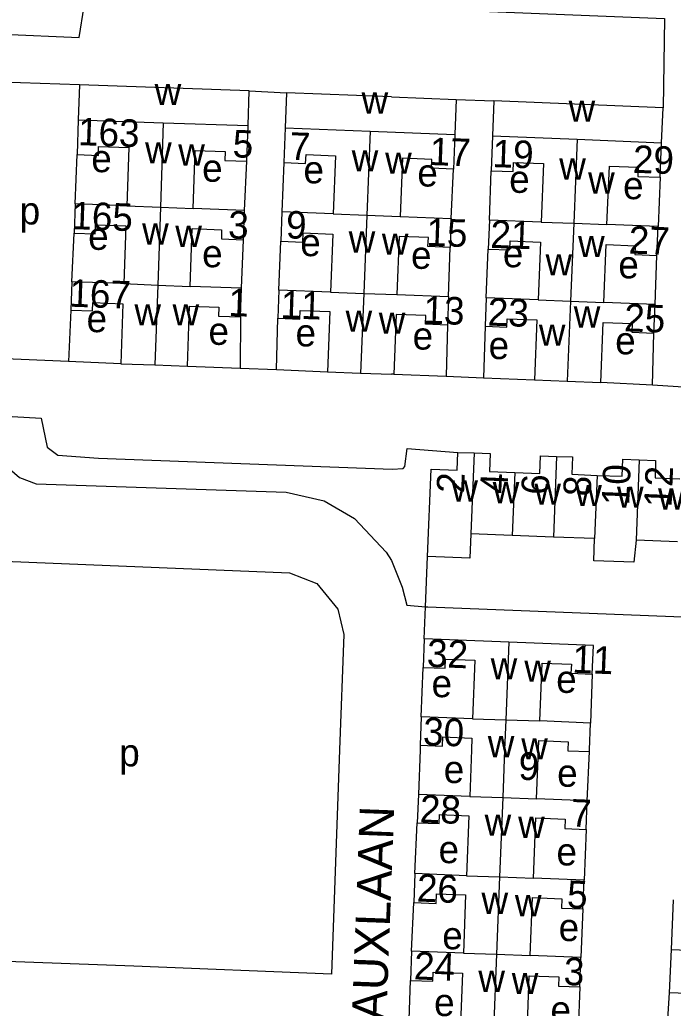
# Model space of a CAD drawing. Extents: x 159675 to 162108, y 386471 to 388472.
# Drawn here: x 160946 to 161040.9, y 387212.5 to 387356.1 of the extents above; entities that cross this region are included whole.
import ezdxf

# ---------------------------------------------------------------- set-up
doc = ezdxf.new("R2010")
doc.units = 0
for name, color, linetype in [('BLT_Basislijn', 7, 'Continuous'), ('BLT_Bebouwing', 7, 'Continuous'), ('BLT_Centroide', 7, 'Continuous'), ('BLT_Huisnummer', 7, 'Continuous'), ('BLT_Huisnummer_ tussenligend', 7, 'Continuous'), ('BLT_Onderverdeling_panden', 7, 'Continuous'), ('BLT_Straatnaam', 7, 'Continuous')]:
    doc.layers.add(name, color=color, linetype=linetype)

msp = doc.modelspace()

# ---------------------------------------------------------------- linework, layer by layer
at = {"layer": 'BLT_Basislijn'}
for p, q in [((160954.66, 387346.6), (160943.23, 387346.99)), ((160979.33, 387345.75), (160984.76, 387345.46)), ((161009.4, 387344.49), (161014.88, 387344.27)), ((160954.01, 387329.31), (160954.32, 387336.48)), ((160978.65, 387328.37), (160978.98, 387335.52)), ((160984.36, 387335.31), (160984.06, 387328.17)), ((161008.67, 387327.19), (161009, 387334.37)), ((161014.22, 387326.97), (161014.47, 387334.14)), ((161039.04, 387333.18), (161038.73, 387326.04)), ((160953.56, 387318.01), (160953.87, 387325.08)), ((160978.2, 387317.05), (160978.51, 387324.11)), ((160983.63, 387316.76), (160983.89, 387323.91)), ((161008.28, 387315.88), (161008.51, 387322.99)), ((161013.74, 387315.68), (161014.05, 387322.75)), ((161038.28, 387314.71), (161038.56, 387321.84)), ((160953.42, 387313.87), (160953.06, 387306.41)), ((160978.06, 387312.92), (160978.02, 387305.45)), ((160983.3, 387305.24), (160983.47, 387312.7)), ((161008.12, 387311.71), (161007.93, 387304.27)), ((161013.58, 387311.53), (161013.38, 387304.06)), ((161037.9, 387302.96), (161038.11, 387310.55)), ((160953.06, 387306.41), (160941.66, 387306.9)), ((160960.67, 387306.09), (160953.06, 387306.41)), ((160970.33, 387305.76), (160978.02, 387305.45)), ((160978.02, 387305.45), (160983.3, 387305.24)), ((160983.3, 387305.24), (160990.68, 387304.94)), ((161000.33, 387304.56), (161007.93, 387304.27)), ((161007.93, 387304.27), (161013.38, 387304.06)), ((161013.38, 387304.06), (161020.75, 387303.77)), ((161037.9, 387302.96), (161030.39, 387303.38)), ((161004.95, 387270.78), (161005.24, 387278.1)), ((161004.76, 387266.11), (161004.95, 387270.78)), ((161004.32, 387254.8), (161004.6, 387261.98)), ((161029.15, 387261.01), (161028.92, 387253.9)), ((161004.16, 387250.67), (161004.14, 387250)), ((161004.14, 387250), (161003.9, 387243.53)), ((161028.42, 387242.59), (161028.76, 387249.76)), ((161003.39, 387232.02), (161003.74, 387239.41)), ((161028.26, 387238.45), (161027.96, 387231.07)), ((161002.92, 387220.78), (161003.23, 387227.83)), ((161040.66, 387221), (161040.94, 387228.2)), ((161027.8, 387226.9), (161027.52, 387219.83)), ((160962.54, 387218.58), (160934, 387219.65)), ((161002.5, 387209.36), (161002.75, 387216.51)), ((161027.35, 387215.56), (161027.08, 387208.44))]:
    msp.add_line(p, q, dxfattribs=at)
for points in [[(160943.5, 387353.98), (160954.59, 387353.47), (160955.32, 387358.02), (160956.82, 387359.41), (160957.39, 387359.57), (161039.67, 387356.23), (161039.45, 387343.28)], [(161043.75, 387314.9), (161043.16, 387302.66), (161037.9, 387302.96)], [(160941.45, 387298.63), (160941.64, 387295.23), (160943.77, 387291.48), (160945.93, 387289.57), (160948.35, 387288.66), (160984.7, 387287.44), (160990.23, 387286.16), (160994.63, 387283.62), (160999.2, 387278.72), (160999.97, 387277.51), (161001.53, 387273.66), (161002.23, 387271.02), (161004.95, 387270.78)], [(160941.45, 387298.63), (160949.1, 387298.21), (160949.94, 387293.99), (160951.5, 387292.8), (160957.41, 387292.36), (161000.11, 387290.8), (161001.67, 387290.86), (161001.91, 387291.15), (161002.26, 387293.76), (161009.65, 387293.22)], [(161004.95, 387270.78), (161005.27, 387270.76), (161101.43, 387266.99), (161101.69, 387277.88)], [(160936.6, 387277.69), (160985.17, 387275.74), (160989.15, 387274.17), (160992.18, 387270.46), (160993.05, 387266.78), (160992.45, 387250)], [(160992.45, 387250), (160991.28, 387217.42), (160962.54, 387218.58)], [(161026.76, 387197.03), (161032.52, 387197.07), (161035.77, 387197.5), (161038.7, 387199.6), (161039.59, 387202.34), (161040.4, 387214.71)]]:
    msp.add_lwpolyline(points, dxfattribs=at)
at = {"layer": 'BLT_Bebouwing'}
for p, q in [((160954.66, 387346.6), (160954.49, 387341.54)), ((160979.33, 387345.75), (160954.66, 387346.6)), ((160979.16, 387340.7), (160979.33, 387345.75)), ((160984.76, 387345.46), (160984.56, 387340.39)), ((161000, 387344.86), (160984.76, 387345.46)), ((161000, 387344.86), (161009.4, 387344.49)), ((161009.4, 387344.49), (161009.2, 387339.42)), ((161014.88, 387344.27), (161014.68, 387339.21)), ((161039.45, 387343.28), (161014.88, 387344.27)), ((161039.24, 387338.21), (161039.45, 387343.28)), ((160954.49, 387341.54), (160954.32, 387336.48)), ((160978.98, 387335.52), (160979.16, 387340.7)), ((160984.56, 387340.39), (160984.36, 387335.31)), ((161009.2, 387339.42), (161009, 387334.37)), ((161014.68, 387339.21), (161014.47, 387334.14)), ((161039.04, 387333.18), (161039.24, 387338.21)), ((160954.01, 387329.31), (160953.87, 387325.08)), ((160961.53, 387329.05), (160954.01, 387329.31)), ((160978.65, 387328.37), (160971.2, 387328.63)), ((160978.51, 387324.11), (160978.65, 387328.37)), ((160984.06, 387328.17), (160983.89, 387323.91)), ((160991.54, 387327.88), (160984.06, 387328.17)), ((161001.26, 387327.48), (161008.67, 387327.19)), ((161008.67, 387327.19), (161008.51, 387322.99)), ((161014.22, 387326.97), (161014.05, 387322.75)), ((161021.75, 387326.66), (161014.22, 387326.97)), ((161038.73, 387326.04), (161031.29, 387326.34)), ((161038.56, 387321.84), (161038.73, 387326.04)), ((160953.56, 387318.01), (160953.42, 387313.87)), ((160961.11, 387317.76), (160953.56, 387318.01)), ((160978.2, 387317.05), (160970.76, 387317.3)), ((160978.06, 387312.92), (160978.2, 387317.05)), ((160983.63, 387316.76), (160983.47, 387312.7)), ((160991.12, 387316.47), (160983.63, 387316.76)), ((161000.79, 387316.17), (161008.28, 387315.88)), ((161008.28, 387315.88), (161008.12, 387311.71)), ((161013.74, 387315.68), (161013.58, 387311.53)), ((161021.3, 387315.37), (161013.74, 387315.68)), ((161038.28, 387314.71), (161030.82, 387315.01)), ((161038.11, 387310.55), (161038.28, 387314.71)), ((160960.67, 387306.09), (160965.63, 387305.92)), ((160965.63, 387305.92), (160970.33, 387305.76)), ((160990.68, 387304.94), (160995.5, 387304.75)), ((160995.5, 387304.75), (161000, 387304.58)), ((161000.33, 387304.56), (161000, 387304.58)), ((161020.75, 387303.77), (161025.53, 387303.58)), ((161025.53, 387303.58), (161030.39, 387303.38)), ((161009.65, 387293.22), (161011.99, 387293.13)), ((161017.53, 387281.16), (161011.53, 387281.39)), ((161023.52, 387280.92), (161017.53, 387281.16)), ((161029.5, 387280.69), (161023.52, 387280.92)), ((161041.54, 387280.22), (161035.54, 387280.46)), ((161004.76, 387266.11), (161004.6, 387261.98)), ((161017.04, 387265.63), (161004.76, 387266.11)), ((161004.32, 387254.8), (161004.16, 387250.67)), ((161011.74, 387254.51), (161004.32, 387254.8)), ((161028.92, 387253.9), (161021.54, 387254.2)), ((161028.77, 387250), (161028.92, 387253.9)), ((161011.62, 387250), (161011.35, 387243.23)), ((161021.08, 387242.88), (161021.36, 387250)), ((161028.76, 387249.76), (161028.77, 387250)), ((161003.9, 387243.53), (161003.74, 387239.41)), ((161011.35, 387243.23), (161003.9, 387243.53)), ((161028.42, 387242.59), (161021.08, 387242.88)), ((161028.26, 387238.45), (161028.42, 387242.59)), ((161003.39, 387232.02), (161003.23, 387227.83)), ((161010.88, 387231.72), (161003.39, 387232.02)), ((161027.96, 387231.07), (161020.62, 387231.36)), ((161027.8, 387226.9), (161027.96, 387231.07)), ((161002.92, 387220.78), (161002.75, 387216.51)), ((161010.43, 387220.49), (161002.92, 387220.78)), ((161040.4, 387214.71), (161040.66, 387221)), ((161040.66, 387221), (161048.8, 387220.67)), ((161027.52, 387219.83), (161020.15, 387220.12)), ((161027.35, 387215.56), (161027.52, 387219.83)), ((161064.83, 387213.7), (161040.4, 387214.71))]:
    msp.add_line(p, q, dxfattribs=at)
for points in [[(160954.32, 387336.48), (160957.4, 387336.37), (160957.44, 387337.65), (160961.82, 387337.5), (160961.53, 387329.05)], [(160971.2, 387328.63), (160971.49, 387337.08), (160975.81, 387336.93), (160975.77, 387335.63), (160978.98, 387335.52)], [(160984.36, 387335.31), (160987.52, 387335.19), (160987.57, 387336.49), (160991.87, 387336.32), (160991.54, 387327.88)], [(161009, 387334.37), (161005.78, 387334.49), (161005.83, 387335.78), (161001.59, 387335.95), (161001.26, 387327.48)], [(161014.47, 387334.14), (161017.67, 387334.01), (161017.73, 387335.34), (161022.09, 387335.17), (161021.75, 387326.66)], [(161031.29, 387326.34), (161031.64, 387334.81), (161035.85, 387334.64), (161035.8, 387333.31), (161039.04, 387333.18)], [(160953.87, 387325.08), (160956.96, 387324.97), (160957.01, 387326.29), (160961.39, 387326.14), (160961.11, 387317.76)], [(160970.76, 387317.3), (160971.05, 387325.72), (160975.31, 387325.57), (160975.27, 387324.22), (160978.51, 387324.11)], [(160983.89, 387323.91), (160987.1, 387323.78), (160987.15, 387325.1), (160991.45, 387324.93), (160991.12, 387316.47)], [(161008.51, 387322.99), (161005.29, 387323.11), (161005.35, 387324.43), (161001.12, 387324.6), (161000.79, 387316.17)], [(161014.05, 387322.75), (161017.2, 387322.62), (161017.25, 387323.96), (161021.64, 387323.78), (161021.3, 387315.37)], [(161030.82, 387315.01), (161031.16, 387323.42), (161035.41, 387323.24), (161035.36, 387321.97), (161038.56, 387321.84)], [(160953.42, 387313.87), (160956.54, 387313.76), (160956.58, 387314.97), (160960.96, 387314.82), (160960.67, 387306.09)], [(160970.33, 387305.76), (160970.63, 387314.45), (160974.89, 387314.31), (160974.84, 387313.03), (160978.06, 387312.92)], [(160983.47, 387312.7), (160986.68, 387312.57), (160986.73, 387313.84), (160991.02, 387313.67), (160990.68, 387304.94)], [(161008.12, 387311.71), (161004.91, 387311.84), (161004.96, 387313.08), (161000.67, 387313.24), (161000.33, 387304.56)], [(161013.58, 387311.53), (161016.76, 387311.4), (161016.81, 387312.63), (161021.11, 387312.45), (161020.75, 387303.77)], [(161030.39, 387303.38), (161030.75, 387312.11), (161034.96, 387311.94), (161034.91, 387310.68), (161038.11, 387310.55)], [(161005.24, 387278.1), (161005.73, 387290.78), (161009.55, 387290.63), (161009.65, 387293.22)], [(161011.99, 387293.13), (161014.33, 387293.04), (161014.22, 387290.43), (161017.89, 387290.29)], [(161017.89, 387290.29), (161021.55, 387290.14), (161021.65, 387292.73), (161023.98, 387292.64)], [(161023.98, 387292.64), (161026.3, 387292.55), (161026.21, 387290.03), (161029.86, 387289.88)], [(161029.86, 387289.88), (161033.51, 387289.74), (161033.61, 387292.22), (161035.99, 387292.13)], [(161035.99, 387292.13), (161038.37, 387292.03), (161038.28, 387289.51), (161041.9, 387289.37)], [(161011.53, 387281.39), (161011.39, 387277.86), (161005.24, 387278.1)], [(161035.54, 387280.46), (161035.19, 387277.26), (161029.38, 387277.48), (161029.5, 387280.69)], [(161029.15, 387261.01), (161029.32, 387265.14), (161017.04, 387265.63)], [(161004.6, 387261.98), (161007.78, 387261.86), (161007.83, 387263.18), (161012.08, 387263.01), (161011.74, 387254.51)], [(161021.54, 387254.2), (161021.87, 387262.62), (161026.12, 387262.46), (161026.07, 387261.13), (161029.15, 387261.01)], [(161004.16, 387250.67), (161007.38, 387250.54), (161007.43, 387251.89), (161011.68, 387251.72), (161011.62, 387250)], [(161021.36, 387250), (161021.42, 387251.36), (161025.65, 387251.19), (161025.61, 387250)], [(161025.61, 387250), (161025.6, 387249.88), (161028.76, 387249.76)], [(161003.74, 387239.41), (161006.92, 387239.29), (161006.98, 387240.6), (161011.22, 387240.43), (161010.88, 387231.72)], [(161020.62, 387231.36), (161020.97, 387240.12), (161025.22, 387239.95), (161025.17, 387238.57), (161028.26, 387238.45)], [(161003.23, 387227.83), (161006.46, 387227.7), (161006.52, 387229.08), (161010.76, 387228.92), (161010.43, 387220.49)], [(161020.15, 387220.12), (161020.49, 387228.54), (161024.76, 387228.37), (161024.71, 387227.02), (161027.8, 387226.9)], [(161002.75, 387216.51), (161005.99, 387216.38), (161006.04, 387217.71), (161010.29, 387217.54), (161009.95, 387209.07)], [(161019.68, 387208.73), (161020.01, 387217.18), (161024.32, 387217.01), (161024.27, 387215.68), (161027.35, 387215.56)]]:
    msp.add_lwpolyline(points, dxfattribs=at)
at = {"layer": 'BLT_Onderverdeling_panden'}
for p, q in [((160954.49, 387341.54), (160966.83, 387341.11)), ((160966.83, 387341.11), (160966.41, 387328.84)), ((160966.83, 387341.11), (160979.16, 387340.7)), ((160984.56, 387340.39), (160996.88, 387339.9)), ((160996.88, 387339.9), (160996.4, 387327.68)), ((160996.88, 387339.9), (161009.2, 387339.42)), ((161014.68, 387339.21), (161026.96, 387338.71)), ((161026.96, 387338.71), (161026.46, 387326.5)), ((161026.96, 387338.71), (161039.24, 387338.21)), ((160961.53, 387329.05), (160966.41, 387328.84)), ((160966.41, 387328.84), (160966.02, 387317.52)), ((160966.41, 387328.84), (160971.2, 387328.63)), ((160991.54, 387327.88), (160996.4, 387327.68)), ((160996.4, 387327.68), (160995.95, 387316.32)), ((160996.4, 387327.68), (161001.26, 387327.48)), ((161021.75, 387326.66), (161026.46, 387326.5)), ((161026.46, 387326.5), (161026.01, 387315.2)), ((161026.46, 387326.5), (161031.29, 387326.34)), ((160961.11, 387317.76), (160966.02, 387317.52)), ((160966.02, 387317.52), (160965.63, 387305.92)), ((160966.02, 387317.52), (160970.76, 387317.3)), ((160991.12, 387316.47), (160995.95, 387316.32)), ((160995.95, 387316.32), (160995.5, 387304.75)), ((160995.95, 387316.32), (161000.79, 387316.17)), ((161021.3, 387315.37), (161026.01, 387315.2)), ((161026.01, 387315.2), (161025.53, 387303.58)), ((161026.01, 387315.2), (161030.82, 387315.01)), ((161011.99, 387293.13), (161011.53, 387281.39)), ((161023.98, 387292.64), (161023.52, 387280.92)), ((161035.99, 387292.13), (161035.54, 387280.46)), ((161017.89, 387290.29), (161017.53, 387281.16)), ((161029.86, 387289.88), (161029.5, 387280.69)), ((161017.04, 387265.63), (161016.59, 387254.36)), ((161011.74, 387254.51), (161016.59, 387254.36)), ((161016.59, 387254.36), (161016.42, 387250)), ((161016.59, 387254.36), (161021.54, 387254.2)), ((161016.42, 387250), (161016.15, 387243.06)), ((161011.35, 387243.23), (161016.15, 387243.06)), ((161016.15, 387243.06), (161015.69, 387231.54)), ((161016.15, 387243.06), (161021.08, 387242.88)), ((161010.88, 387231.72), (161015.69, 387231.54)), ((161015.69, 387231.54), (161015.25, 387220.3)), ((161015.69, 387231.54), (161020.62, 387231.36)), ((161010.43, 387220.49), (161015.25, 387220.3)), ((161015.25, 387220.3), (161014.8, 387208.9)), ((161015.25, 387220.3), (161020.15, 387220.12))]:
    msp.add_line(p, q, dxfattribs=at)

# ---------------------------------------------------------------- texts
at = {"layer": 'BLT_Centroide'}
for s, p in [('w', (160965.58, 387343.66)), ('w', (160995.64, 387342.44)), ('w', (161025.72, 387341.25)), ('w', (160964.19, 387335.19)), ('e', (160956.38, 387333.92)), ('w', (160969.01, 387334.88)), ('w', (160994.21, 387334.03)), ('w', (160999.07, 387333.69)), ('e', (160972.48, 387332.53)), ('e', (160987.2, 387332.3)), ('w', (161024.36, 387332.84)), ('e', (161003.75, 387331.84)), ('e', (161017.09, 387330.92)), ('w', (161028.56, 387330.82)), ('e', (161033.64, 387330)), ('p', (160945.97, 387326.33)), ('e', (160955.92, 387322.64)), ('w', (160963.76, 387323.41)), ('w', (160968.58, 387323.06)), ('w', (160993.77, 387322.25)), ('e', (160986.74, 387321.72)), ('w', (160998.59, 387321.94)), ('w', (161027.1, 387321.58)), ('e', (160972.48, 387320.11)), ('e', (161002.83, 387319.88)), ('e', (161016.17, 387320.11)), ('w', (161022.37, 387318.94)), ('e', (161032.95, 387318.5)), ('e', (160955.69, 387310.68)), ('w', (160962.64, 387311.66)), ('w', (160968.18, 387311.66)), ('w', (160993.32, 387310.75)), ('w', (161026.47, 387311.36)), ('w', (160998.14, 387310.44)), ('e', (160973.4, 387308.84)), ('e', (160986.05, 387308.61)), ('e', (161003.06, 387308.15)), ('w', (161021.4, 387308.72)), ('e', (161014.1, 387306.77)), ('e', (161032.49, 387307.46)), ('w', (161008.69, 387286.08)), ('w', (161014.7, 387285.84)), ('w', (161020.75, 387285.61)), ('w', (161026.69, 387285.41)), ('w', (161032.75, 387285.17)), ('w', (161038.72, 387284.92)), ('w', (161014.4, 387260.25)), ('w', (161019.29, 387259.91)), ('e', (161005.81, 387257.65)), ('e', (161023.92, 387258.28)), ('w', (161013.98, 387248.94)), ('p', (160960.44, 387247.6)), ('w', (161018.84, 387248.62)), ('e', (161007.58, 387245.18)), ('e', (161024.06, 387244.64)), ('w', (161013.52, 387237.53)), ('w', (161018.39, 387237.22)), ('e', (161006.83, 387233.54)), ('e', (161023.96, 387233.21)), ('w', (161013.07, 387226.16)), ('w', (161017.92, 387225.84)), ('e', (161024.28, 387222.22)), ('e', (161007.37, 387221.03)), ('w', (161012.61, 387214.84)), ('w', (161017.46, 387214.53)), ('e', (161006.18, 387211.33)), ('e', (161023.09, 387210.25))]:
    msp.add_text(s, height=4, dxfattribs=at).set_placement(p)
at = {"layer": 'BLT_Huisnummer'}
for s, rotation, p in [('163', 358.0475, (160954.4, 387337.86)), ('5', 358.0501, (160976.87, 387336.09)), ('7', 358.0501, (160985.15, 387335.73)), ('17', 358.0501, (161005.48, 387334.97)), ('19', 358.0501, (161014.62, 387334.67)), ('29', 358.0501, (161035.01, 387333.84)), ('165', 358.0475, (160953.43, 387325.66)), ('3', 358.0501, (160976.21, 387324.3)), ('9', 358.0501, (160984.61, 387324.32)), ('15', 358.0501, (161005.01, 387323.24)), ('21', 358.0501, (161014.31, 387322.94)), ('27', 358.0501, (161034.4, 387322.11)), ('167', 358.0475, (160953.14, 387314.39)), ('1', 358.0501, (160976.24, 387313.04)), ('11', 358.0501, (160983.83, 387312.71)), ('13', 358.0501, (161004.59, 387311.94)), ('23', 358.0501, (161013.92, 387311.65)), ('25', 358.0501, (161033.75, 387310.81)), ('10', 87.77, (161034.52, 387285.48)), ('2', 87.77, (161010.53, 387287.24)), ('6', 87.77, (161022.83, 387287)), ('32', 357.728, (161005.08, 387262.08)), ('11', 357.7304, (161026.21, 387261.22)), ('30', 357.728, (161004.52, 387250.71)), ('9', 357.7304, (161018.38, 387245.68)), ('28', 357.728, (161004.05, 387239.47)), ('7', 357.7304, (161025.99, 387238.87)), ('26', 357.728, (161003.62, 387227.98)), ('5', 357.7304, (161025.44, 387227.05)), ('24', 357.728, (161003.2, 387216.67)), ('3', 357.7304, (161024.96, 387215.86))]:
    msp.add_text(s, height=4, rotation=rotation, dxfattribs=at).set_placement(p)
at = {"layer": 'BLT_Huisnummer_ tussenligend'}
for s, p in [('12', (161040.68, 387285.2)), ('4', (161016.84, 387287.15)), ('8', (161028.93, 387286.78))]:
    msp.add_text(s, height=4, rotation=87.77, dxfattribs=at).set_placement(p)
at = {"layer": 'BLT_Straatnaam'}
msp.add_text('CLERVAUXLAAN', height=5, rotation=87.8416, dxfattribs=at).set_placement((160998.38, 387188.28))

doc.saveas('drawing.dxf')
